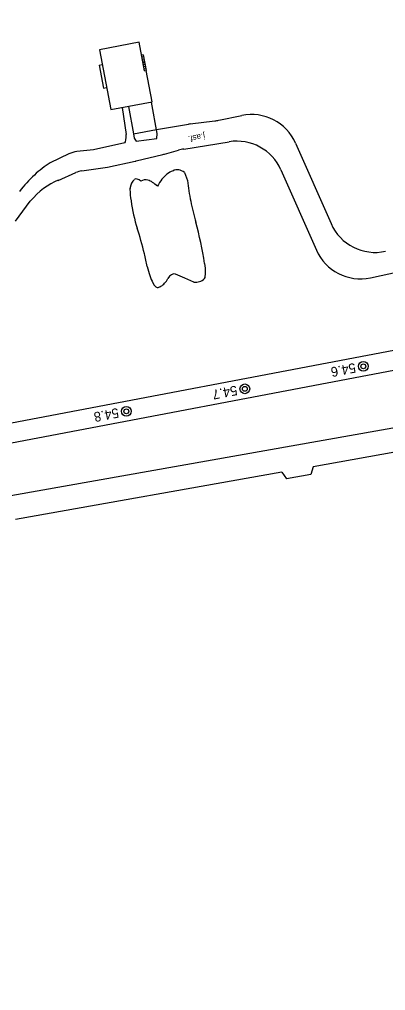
# Model space of a CAD drawing. Extents: x 6541740 to 6566395, y 5525066 to 5530361.
# Drawn here: x 6558824.2 to 6558900.1, y 5526356.1 to 5526557.1 of the extents above; entities that cross this region are included whole.
import ezdxf

# ---------------------------------------------------------------- set-up
doc = ezdxf.new("R2010")
doc.units = 0
for name, color, linetype in [('Domyślna', 7, 'Continuous'), ('ps_wymiarowanie', 7, 'Continuous'), ('TOR_PRZEK_P-komponent', 7, 'Continuous'), ('TOR_PRZEK_P-teren istniejacy', 7, 'Continuous'), ('TOR_PS_OPIS_T-symbole geometrii', 7, 'Continuous'), ('TOR_PS_T-wypelnienia', 7, 'Continuous'), ('TOR_RAMKI-ramka+tabelka 1', 7, 'Continuous')]:
    doc.layers.add(name, color=color, linetype=linetype)

# ---------------------------------------------------------------- blocks, each defined once
blk = doc.blocks.new('4010_1')
at = {"layer": 'Domyślna'}
for radius in [0.75, 0.375]:
    blk.add_circle((0, 0), radius, dxfattribs=at)

msp = doc.modelspace()

# ---------------------------------------------------------------- linework, layer by layer
at = {"layer": 'Domyślna'}
for p, q in [((6558858.4, 5526525.46), (6558859.02, 5526523.77)), ((6558858.4, 5526525.46), (6558859.02, 5526523.77)), ((6558858.51, 5526503.56), (6558856.55, 5526504.41)), ((6558858.51, 5526503.56), (6558856.55, 5526504.41)), ((6558860.36, 5526502.77), (6558858.51, 5526503.56)), ((6558860.36, 5526502.77), (6558858.51, 5526503.56))]:
    msp.add_line(p, q, dxfattribs=at)
for centre, major_axis, start_param, end_param in [((6558866.71, 5526471.36), (-10.33, 54.5), 0.031092, 0.123696), ((6558866.71, 5526471.36), (-10.33, 54.5), 0.031092, 0.123696), ((6558861.65, 5526499.22), (-5.07, 26.77), 6.183628, 6.378104), ((6558861.65, 5526499.22), (-5.07, 26.77), 6.183628, 6.378104), ((6558861.65, 5526499.22), (-5.07, 26.77), 6.031553, 6.183625), ((6558861.65, 5526499.22), (-5.07, 26.77), 6.031553, 6.183625), ((6558850.56, 5526512.24), (-2.25, 11.86), 0.110236, 0.569344), ((6558850.56, 5526512.24), (-2.25, 11.86), 0.110236, 0.569344), ((6558850.56, 5526512.24), (-2.25, 11.87), 5.962189, 6.393418), ((6558850.56, 5526512.24), (-2.25, 11.87), 5.962189, 6.393418), ((6558855.5, 5526494.59), (-5.55, 29.3), 6.165536, 6.365657), ((6558855.5, 5526494.59), (-5.55, 29.3), 6.165536, 6.365657), ((6558855.5, 5526494.59), (-5.55, 29.3), 5.933796, 6.165533), ((6558855.5, 5526494.59), (-5.55, 29.3), 5.933796, 6.165533), ((6558866.67, 5526471.57), (-10.29, 54.28), 0.123808, 0.303953), ((6558866.67, 5526471.57), (-10.29, 54.28), 0.123808, 0.303953), ((6558863.42, 5526520.77), (-2.89, 15.25), 1.325555, 1.607283), ((6558863.42, 5526520.77), (-2.89, 15.25), 1.325555, 1.607283), ((6558850.56, 5526512.24), (-2.25, 11.87), 0.469826, 0.569326), ((6558850.56, 5526512.24), (-2.25, 11.87), 0.469826, 0.569326), ((6558850.18, 5526518.38), (-1.94, 10.23), 1.169627, 1.406274), ((6558850.18, 5526518.38), (-1.94, 10.23), 1.169627, 1.406274), ((6558850.15, 5526518.38), (-1.92, 10.14), 1.404882, 1.97915), ((6558850.15, 5526518.38), (-1.92, 10.14), 1.404882, 1.97915), ((6558863.42, 5526520.77), (-2.89, 15.25), 1.607288, 1.90072), ((6558863.42, 5526520.77), (-2.89, 15.25), 1.607288, 1.90072), ((6558846.45, 5526504.65), (-3.28, 17.3), 4.897367, 5.229267), ((6558846.45, 5526504.65), (-3.28, 17.3), 4.897367, 5.229267), ((6558856.71, 5526507.65), (-4.18, 22.07), 4.61884, 5.011338), ((6558856.71, 5526507.65), (-4.18, 22.07), 4.61884, 5.011338), ((6558846.18, 5526504.4), (-3.51, 18.54), 4.7503, 4.895617), ((6558846.18, 5526504.4), (-3.51, 18.54), 4.7503, 4.895617), ((6558851.87, 5526507.16), (-1.05, 5.53), 1.737836, 2.48217), ((6558851.87, 5526507.16), (-1.05, 5.53), 1.737836, 2.48217), ((6558861.72, 5526506.65), (-0.64, 3.37), 3.451558, 4.657786), ((6558861.72, 5526506.65), (-0.64, 3.37), 3.451558, 4.657786), ((6558846.45, 5526535.28), (-6.38, 33.66), 3.228321, 3.433984), ((6558846.45, 5526535.28), (-6.38, 33.66), 3.228321, 3.433984), ((6558859.32, 5526487.24), (-3.26, 17.19), 6.17408, 6.567878), ((6558859.32, 5526487.24), (-3.26, 17.19), 6.17408, 6.567878), ((6558853.69, 5526542.5), (-7.53, 39.71), 3.05813, 3.288232), ((6558853.69, 5526542.5), (-7.53, 39.71), 3.05813, 3.288232), ((6558851.87, 5526507.16), (-1.05, 5.53), 2.482174, 3.188431), ((6558851.87, 5526507.16), (-1.05, 5.53), 2.482174, 3.188431), ((6558846.45, 5526535.29), (-6.38, 33.67), 3.159571, 3.228317), ((6558846.45, 5526535.29), (-6.38, 33.67), 3.159571, 3.228317)]:
    msp.add_ellipse(centre, major_axis=major_axis, ratio=0.25, start_param=start_param, end_param=end_param, dxfattribs=at)
at = {"layer": 'ps_wymiarowanie'}
for p, q in [((6558849.01, 5526552.41), (6558840.77, 5526550.83)), ((6558849.01, 5526552.41), (6558840.77, 5526550.83)), ((6558850.13, 5526546.53), (6558849.01, 5526552.41)), ((6558850.13, 5526546.53), (6558849.01, 5526552.41)), ((6558840.77, 5526550.83), (6558843.12, 5526538.47)), ((6558840.77, 5526550.83), (6558843.12, 5526538.47)), ((6558849.83, 5526549.8), (6558849.52, 5526549.74)), ((6558849.83, 5526549.8), (6558849.52, 5526549.74)), ((6558849.83, 5526549.8), (6558850.44, 5526546.57)), ((6558849.83, 5526549.8), (6558850.44, 5526546.57)), ((6558840.71, 5526547.66), (6558841.35, 5526547.79)), ((6558840.71, 5526547.66), (6558841.35, 5526547.79)), ((6558840.71, 5526547.66), (6558841.6, 5526542.94)), ((6558840.71, 5526547.66), (6558841.6, 5526542.94)), ((6558849.9, 5526549.39), (6558849.6, 5526549.34)), ((6558849.9, 5526549.39), (6558849.6, 5526549.34)), ((6558849.67, 5526548.93), (6558849.98, 5526548.99)), ((6558849.67, 5526548.93), (6558849.98, 5526548.99)), ((6558849.75, 5526548.53), (6558850.06, 5526548.59)), ((6558849.75, 5526548.53), (6558850.06, 5526548.59)), ((6558850.13, 5526548.18), (6558849.83, 5526548.13)), ((6558850.13, 5526548.18), (6558849.83, 5526548.13)), ((6558850.21, 5526547.78), (6558849.9, 5526547.73)), ((6558850.21, 5526547.78), (6558849.9, 5526547.73)), ((6558850.29, 5526547.38), (6558849.98, 5526547.33)), ((6558850.29, 5526547.38), (6558849.98, 5526547.33)), ((6558850.06, 5526546.93), (6558850.37, 5526546.97)), ((6558850.06, 5526546.93), (6558850.37, 5526546.97)), ((6558850.13, 5526546.53), (6558850.44, 5526546.57)), ((6558850.13, 5526546.53), (6558850.44, 5526546.57)), ((6558851.69, 5526540.05), (6558850.44, 5526546.57)), ((6558851.69, 5526540.05), (6558850.44, 5526546.57)), ((6558841.6, 5526542.94), (6558842.25, 5526543.07)), ((6558841.6, 5526542.94), (6558842.25, 5526543.07)), ((6558843.12, 5526538.47), (6558851.69, 5526540.05)), ((6558843.12, 5526538.47), (6558851.69, 5526540.05)), ((6558852.75, 5526533.51), (6558851.55, 5526540.02)), ((6558852.75, 5526533.51), (6558851.55, 5526540.02)), ((6558847.85, 5526533.48), (6558852.59, 5526534.38)), ((6558847.85, 5526533.48), (6558852.59, 5526534.38)), ((6558847.85, 5526533.48), (6558848.01, 5526532.56)), ((6558847.85, 5526533.48), (6558848.01, 5526532.56)), ((6558852.66, 5526532.52), (6558852.75, 5526533.51)), ((6558852.66, 5526532.52), (6558852.75, 5526533.51)), ((6558848.01, 5526532.56), (6558848.38, 5526531.92)), ((6558848.01, 5526532.56), (6558848.38, 5526531.92)), ((6558848.38, 5526531.92), (6558852.66, 5526532.52)), ((6558848.38, 5526531.92), (6558852.66, 5526532.52))]:
    msp.add_line(p, q, dxfattribs=at)
for centre, radius, start, end in [((6558860.82, 5526525.59), 10, 97.1358, 99.2571), ((6558860.82, 5526525.59), 10, 97.1358, 99.2571), ((6558863.48, 5526546.08), 10, 277.1358, 281.6221), ((6558863.48, 5526546.08), 10, 277.1358, 281.6221), ((6558836.63, 5526524.81), 5, 95.8243, 115.8913), ((6558836.63, 5526524.81), 5, 95.8243, 115.8913), ((6558837.86, 5526520.83), 5, 98.3641, 113.3976), ((6558837.86, 5526520.83), 5, 98.3641, 113.3976)]:
    msp.add_arc(centre, radius, start, end, dxfattribs=at)
at = {"layer": 'TOR_PRZEK_P-komponent'}
for p, q in [((6559263.55, 5526557.15), (6557908.19, 5526300.24)), ((6559264.3, 5526553.17), (6558036.17, 5526320.37))]:
    msp.add_line(p, q, dxfattribs=at)
at = {"layer": 'TOR_PS_OPIS_T-symbole geometrii'}
for p, q in [((6559028.98, 5526495.09), (6558822.42, 5526458.53)), ((6559028.98, 5526495.09), (6558822.42, 5526458.53)), ((6559021.4, 5526488.67), (6558885.06, 5526464.54)), ((6559021.4, 5526488.67), (6558885.06, 5526464.54)), ((6558878.57, 5526463.4), (6558823.35, 5526453.62)), ((6558878.57, 5526463.4), (6558823.35, 5526453.62)), ((6558878.57, 5526463.4), (6558879.59, 5526462.05)), ((6558878.57, 5526463.4), (6558879.59, 5526462.05)), ((6558885.06, 5526464.54), (6558884.6, 5526462.94)), ((6558885.06, 5526464.54), (6558884.6, 5526462.94)), ((6558884.6, 5526462.94), (6558879.59, 5526462.05)), ((6558884.6, 5526462.94), (6558879.59, 5526462.05))]:
    msp.add_line(p, q, dxfattribs=at)
at = {"layer": 'TOR_PS_T-wypelnienia'}
for p, q in [((6558845.47, 5526538.88), (6558846.32, 5526533.32)), ((6558845.47, 5526538.88), (6558846.32, 5526533.32)), ((6558846.81, 5526539.13), (6558847.85, 5526533.48)), ((6558846.81, 5526539.13), (6558847.85, 5526533.48)), ((6558852.59, 5526534.38), (6558859.21, 5526535.46)), ((6558852.59, 5526534.38), (6558859.21, 5526535.46)), ((6558859.58, 5526535.51), (6558864.72, 5526536.15)), ((6558859.58, 5526535.51), (6558864.72, 5526536.15)), ((6558865.5, 5526536.28), (6558870.27, 5526537.26)), ((6558865.5, 5526536.28), (6558870.27, 5526537.26)), ((6558846.03, 5526531.59), (6558839.52, 5526530.13)), ((6558846.03, 5526531.59), (6558839.52, 5526530.13)), ((6558858.3, 5526530.31), (6558867.68, 5526531.81)), ((6558858.3, 5526530.31), (6558867.68, 5526531.81)), ((6558881.43, 5526531.51), (6558888.8, 5526514.86)), ((6558881.43, 5526531.51), (6558888.8, 5526514.86)), ((6558839.52, 5526530.13), (6558836.12, 5526529.78)), ((6558839.52, 5526530.13), (6558836.12, 5526529.78)), ((6558854.3, 5526529.26), (6558857.2, 5526530.07)), ((6558854.3, 5526529.26), (6558857.2, 5526530.07)), ((6558834.45, 5526529.31), (6558830.58, 5526527.43)), ((6558834.45, 5526529.31), (6558830.58, 5526527.43)), ((6558842.42, 5526526.55), (6558848.2, 5526527.8)), ((6558842.42, 5526526.55), (6558848.2, 5526527.8)), ((6558848.4, 5526527.85), (6558853.94, 5526529.17)), ((6558848.4, 5526527.85), (6558853.94, 5526529.17)), ((6558832.22, 5526523.83), (6558835.88, 5526525.42)), ((6558832.22, 5526523.83), (6558835.88, 5526525.42)), ((6558837.14, 5526525.77), (6558842.42, 5526526.55)), ((6558837.14, 5526525.77), (6558842.42, 5526526.55)), ((6558878.41, 5526525.99), (6558885.75, 5526509.39)), ((6558878.41, 5526525.99), (6558885.75, 5526509.39)), ((6558823.36, 5526515.35), (6558826.44, 5526519.49)), ((6558823.36, 5526515.35), (6558826.44, 5526519.49)), ((6558896.96, 5526503.66), (6558902.98, 5526504.93)), ((6558896.96, 5526503.66), (6558902.98, 5526504.93))]:
    msp.add_line(p, q, dxfattribs=at)
for centre, start, end in [((6558872.29, 5526527.47), 23.8612, 101.6221), ((6558872.29, 5526527.47), 23.8612, 101.6221), ((6558869.27, 5526521.94), 23.8612, 99.1064), ((6558869.27, 5526521.94), 23.8612, 99.1064), ((6558859.88, 5526520.44), 99.1064, 105.5381), ((6558859.88, 5526520.44), 99.1064, 105.5381), ((6558846.08, 5526537.58), 282.2304, 283.4211), ((6558846.08, 5526537.58), 282.2304, 283.4211), ((6558851.62, 5526538.9), 283.4211, 285.5381), ((6558851.62, 5526538.9), 283.4211, 285.5381), ((6558897.94, 5526518.91), 203.8612, 282.4602), ((6558897.94, 5526518.91), 203.8612, 282.4602), ((6558894.89, 5526513.44), 203.8612, 281.9343), ((6558894.89, 5526513.44), 203.8612, 281.9343)]:
    msp.add_arc(centre, 10, start, end, dxfattribs=at)
for centre, major_axis, start_param, end_param in [((6558845.24, 5526534.99), (-0.66, 3.47), 3.299182, 4.163901), ((6558845.24, 5526534.99), (-0.66, 3.47), 3.299182, 4.163901), ((6558881.96, 5526287.46), (-45.89, 242.12), 0.093991, 0.215261), ((6558881.96, 5526287.46), (-45.89, 242.12), 0.093991, 0.215261), ((6558866.11, 5526355.69), (-31.98, 168.69), 0.046191, 0.198595), ((6558866.11, 5526355.69), (-31.98, 168.69), 0.046191, 0.198595)]:
    msp.add_ellipse(centre, major_axis=major_axis, ratio=0.25, start_param=start_param, end_param=end_param, dxfattribs=at)

# ---------------------------------------------------------------- block references
at = {"layer": 'TOR_RAMKI-ramka+tabelka 1', "xscale": 1.345963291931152, "yscale": 1.345963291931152}
for p in [(6558895.49, 5526485.32), (6558870.92, 5526480.66), (6558846.36, 5526476.01)]:
    msp.add_blockref('4010_1', p, dxfattribs=at)

# ---------------------------------------------------------------- texts
at = {"layer": 'TOR_PRZEK_P-teren istniejacy'}
msp.add_text('j.asf.', height=1.25, rotation=190.7928, dxfattribs=at).set_placement((6558862.56, 5526533.61))
msp.add_text('j.asf.', height=1.25, rotation=190.7928, dxfattribs=at).set_placement((6558862.56, 5526533.61))
at = {"layer": 'TOR_RAMKI-ramka+tabelka 1'}
for s, p in [('54.6', (6558893.71, 5526486.03)), ('54.7', (6558869.15, 5526481.36)), ('54.8', (6558844.59, 5526476.71))]:
    msp.add_text(s, height=2, rotation=190.7691, dxfattribs=at).set_placement(p)

doc.saveas('drawing.dxf')
